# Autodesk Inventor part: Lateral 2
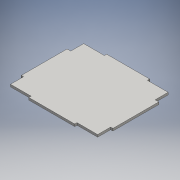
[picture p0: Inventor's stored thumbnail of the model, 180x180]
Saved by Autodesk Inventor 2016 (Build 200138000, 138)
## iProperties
Created: 2016-06
Part Number: Lateral 2
Material: Genérico
Document SubType Name: Modeling
Designer: adm
Density: 1 g/cm^3
Appearance: Valor por defecto
Author: adm
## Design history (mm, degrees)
sketch "Boceto1"
  geometry: L1 (0, 50)-(28.229, 50); L2 (60, 30)-(60, -30); L3 (30, -50)-(0, -50); L4 (57, -46.983)-(57, -30); L5 (55.229, 30)-(55.229, 47); L6 (55.229, 47)-(28.229, 47); L7 (30, -46.983)-(57, -46.983); L8 (30, -46.983)-(30, -50); L9 (28.229, 50)-(28.229, 47); L10 (57, -30)-(60, -30); L11 (55.229, 30)-(60, 30); L12 (0, 50)-(-28.229, 50); L13 (-60, 30)-(-60, -30); L14 (-30, -50)-(0, -50); L15 (-57, -47)-(-57, -30); L16 (-55.229, 30)-(-55.229, 47); L17 (-55.229, 47)-(-28.229, 47); L18 (-30, -47)-(-57, -47); L19 (-30, -47)-(-30, -50); L20 (-28.229, 50)-(-28.229, 47); L21 (-57, -30)-(-60, -30); L22 (-55.229, 30)-(-60, 30); 1 further point
  constraints: 44 end point, 3 perpendicular, 2 parallel, 1 horizontal
  dimensions: "d0" = 94 distance of L4.start L5.end; "d1" = 3 distance between parallel lines of L6 L1; "d8" = 60 distance between parallel lines of L21 L22; "d9" = 17 distance between parallel lines of L22 L17; "d10" = 17 distance between parallel lines of L21 L18; "d11" = 60 distance of L2.start L2.end; "d13" = 17 distance between parallel lines of L11 L6
extrude "Extrusión1" new body sketch "Boceto1" distance "d2" = 3; taper "d3" = 0 deg
node "Sólido1"
